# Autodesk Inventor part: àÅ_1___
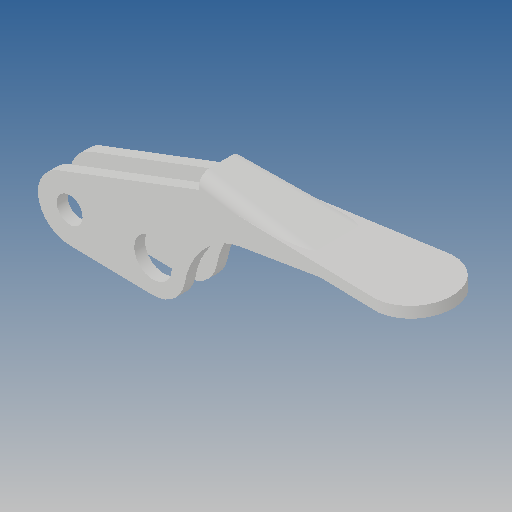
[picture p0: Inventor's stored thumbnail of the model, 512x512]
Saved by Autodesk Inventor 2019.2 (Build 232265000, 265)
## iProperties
Created: 2010-06
Part Number: àÅ_1___
Material: Ogólny
Document SubType Name: Modeling
Designer: CADENGINEERING4
Density: 1 g/cm^3
Appearance: Domyślna
Author: CADENGINEERING4
Revision Number: ANY
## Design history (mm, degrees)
feature "NONE"
node "Bryła1"
